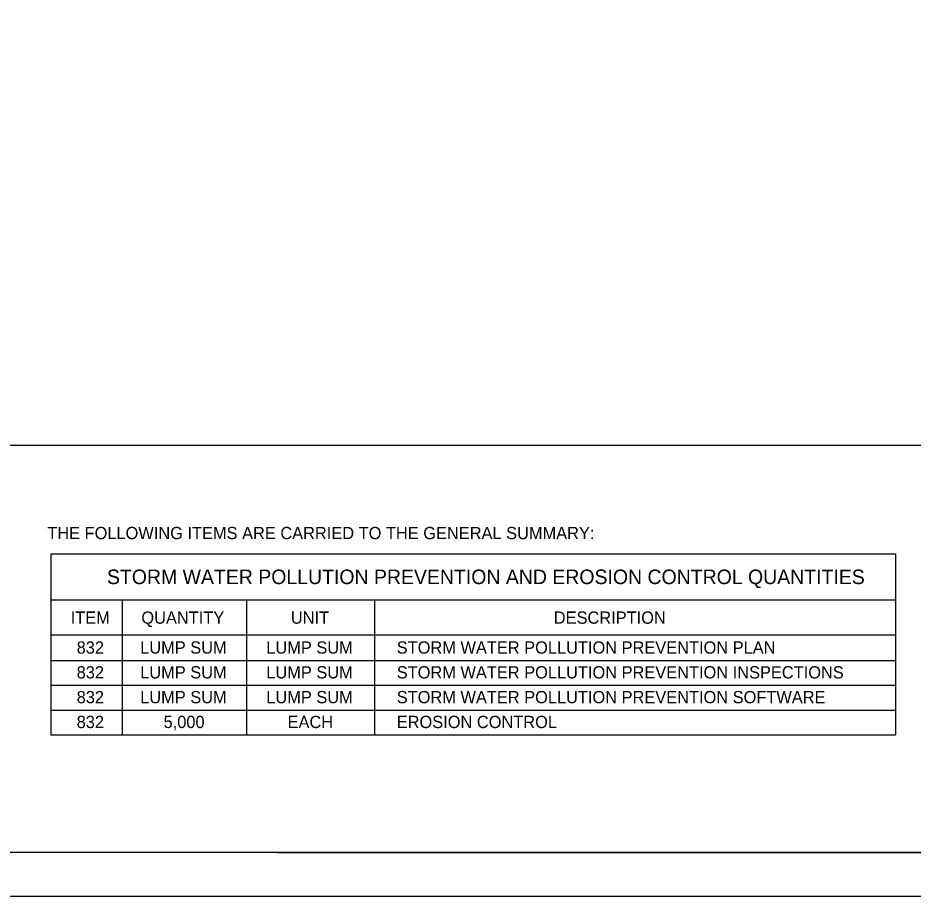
# Model space of a CAD drawing. Extents: x 0 to 1700, y 0 to 1100.
# Drawn here: x 695 to 1206, y 0 to 502 of the extents above; entities that cross this region are included whole.
import ezdxf

# ---------------------------------------------------------------- set-up
doc = ezdxf.new("R2010")
doc.units = 0
for name, color, linetype in [('DT_X_Contour_Major', 7, 'Continuous'), ('DT_X_Contour_Minor', 7, 'Continuous'), ('DT_X_Contour_Text', 7, 'Continuous'), ('DT_X_Terrain_Ground_Line', 7, 'Continuous')]:
    doc.layers.add(name, color=color, linetype=linetype)

msp = doc.modelspace()

# ---------------------------------------------------------------- linework, layer by layer
at = {"layer": 'DT_X_Contour_Major'}
msp.add_lwpolyline([(85, 883.45), (688.26, 883.45), (688.26, 1062.5), (1590, 1062.5), (1590, 257.42), (593.29, 257.42), (593.29, 340.4), (85, 340.4)], close=True, dxfattribs=at)
at = {"layer": 'DT_X_Contour_Minor'}
msp.add_lwpolyline([(75, 1075), (1675, 1075), (1675, 25), (75, 25)], close=True, dxfattribs=at)
at = {"layer": 'DT_X_Contour_Text'}
for p, q in [((713.25, 195.51), (1195.85, 195.51)), ((713.25, 195.51), (713.25, 92.12)), ((1195.85, 195.51), (1195.85, 92.12)), ((713.25, 169.32), (1195.85, 169.32)), ((754, 169.32), (754, 92.12)), ((825.11, 169.32), (825.11, 92.12)), ((898.29, 169.32), (898.29, 92.12)), ((713.25, 149.21), (1195.85, 149.21)), ((713.25, 134.64), (1195.85, 134.64)), ((713.25, 120.46), (1195.85, 120.46)), ((713.25, 106.29), (1195.85, 106.29)), ((713.25, 92.12), (1195.85, 92.12)), ((842.76, 25), (1600, 25))]:
    msp.add_line(p, q, dxfattribs=at)
at = {"layer": 'DT_X_Terrain_Ground_Line'}
msp.add_lwpolyline([(0, 0), (1700, 0), (1700, 1100), (0, 1100)], close=True, dxfattribs=at)

# ---------------------------------------------------------------- texts
at = {"layer": 'DT_X_Contour_Text'}
for s, height, p in [('THE FOLLOWING ITEMS ARE CARRIED TO THE GENERAL SUMMARY:', 7, (711.29, 203.91)), ('STORM WATER POLLUTION PREVENTION AND EROSION CONTROL QUANTITIES', 8.3125, (745.37, 178.23)), ('ITEM', 7, (724.66, 155.59)), ('QUANTITY', 7, (765.04, 155.59)), ('UNIT', 7, (850.45, 155.59)), ('DESCRIPTION', 7, (1000.64, 155.59)), ('832', 7, (728.07, 138.51)), ('LUMP SUM', 7, (764.37, 138.51)), ('LUMP SUM', 7, (836.4, 138.51)), ('STORM WATER POLLUTION PREVENTION PLAN', 7, (910.93, 138.51)), ('832', 7, (728.07, 124.34)), ('LUMP SUM', 7, (764.37, 124.34)), ('LUMP SUM', 7, (836.4, 124.34)), ('STORM WATER POLLUTION PREVENTION INSPECTIONS', 7, (910.93, 124.34)), ('832', 7, (728.07, 110.17)), ('LUMP SUM', 7, (764.37, 110.17)), ('LUMP SUM', 7, (836.4, 110.17)), ('STORM WATER POLLUTION PREVENTION SOFTWARE', 7, (910.93, 110.17)), ('832', 7, (728.07, 96)), ('5,000', 7, (777.73, 96)), ('EACH', 7, (848.57, 96)), ('EROSION CONTROL', 7, (910.93, 96))]:
    msp.add_text(s, height=height, dxfattribs=at).set_placement(p)

doc.saveas('drawing.dxf')
